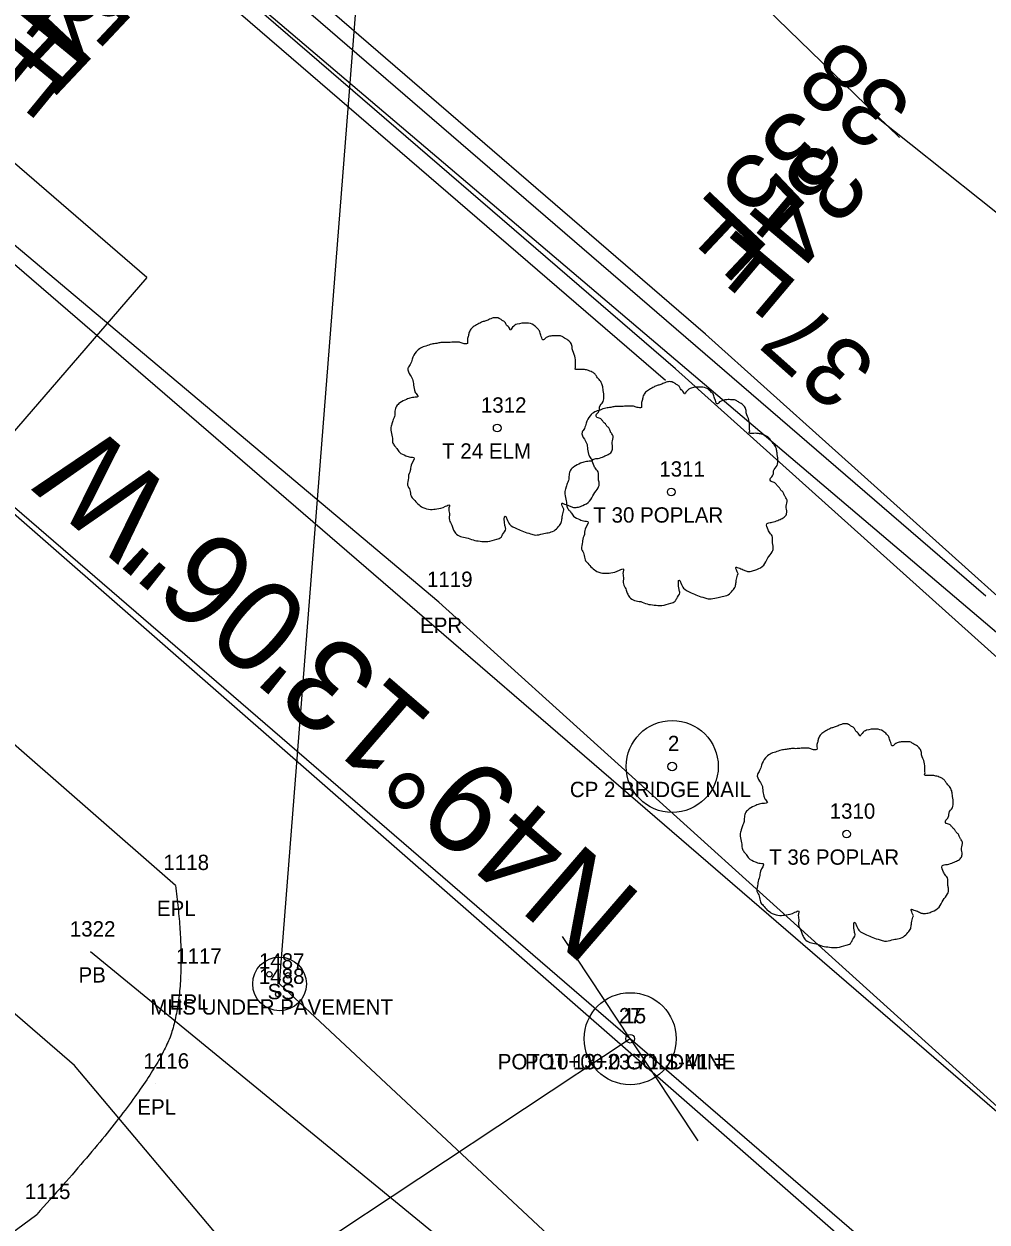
# Model space of a CAD drawing. Extents: x 1812113 to 1819860, y 1177395 to 1181185.
# Drawn here: x 1813790.4 to 1813853.2, y 1178629.6 to 1178707.7 of the extents above; entities that cross this region are included whole.
import ezdxf

# ---------------------------------------------------------------- set-up
doc = ezdxf.new("R2010")
doc.units = 0
for name, color, linetype in [('RD_EX_DR_Inlet', 7, 'Continuous'), ('RD_EX_DR_Pipe', 7, 'Continuous'), ('RD_EX_DR_Pipe_txCode', 7, 'Continuous'), ('RD_EX_DV_Prop', 7, 'Continuous'), ('RD_EX_Road', 7, 'Continuous'), ('RD_EX_Road_txCode', 7, 'Continuous'), ('RD_EX_UT', 7, 'Continuous'), ('RD_EX_UT_txCode', 7, 'Continuous'), ('RD_EX_VEG', 7, 'Continuous'), ('RD_EX_VEG_txCode', 7, 'Continuous'), ('RD_HC_CL', 7, 'Continuous'), ('RD_HC_Data', 7, 'Continuous'), ('RD_HC_Data_Tic', 7, 'Continuous'), ('RD_HC_txCode', 7, 'Continuous'), ('RD_PD_ALT1_TrvlWay', 7, 'Continuous'), ('RD_PD_ALT3_LnLine', 7, 'Continuous'), ('RD_PD_ALT4_LnLine', 7, 'Continuous'), ('RD_PD_BCA', 7, 'Continuous'), ('RD_PD_Bridge', 7, 'Continuous'), ('RD_PD_PatLn1', 7, 'Continuous'), ('RD_SMD_Locator', 7, 'Continuous')]:
    doc.layers.add(name, color=color, linetype=linetype)

msp = doc.modelspace()

# ---------------------------------------------------------------- linework, layer by layer
at = {"layer": 'RD_EX_DR_Inlet'}
for centre, radius in [((1813807.047, 1178645.143), 1.75), ((1813806.382, 1178645.773), 0.175), ((1813807.607, 1178645.703), 0.175), ((1813806.959, 1178644.478), 0.175)]:
    msp.add_circle(centre, radius, dxfattribs=at)
at = {"layer": 'RD_EX_DR_Pipe'}
msp.add_line((1813831.42, 1178617.18), (1813794.721, 1178647.236), dxfattribs=at)
at = {"layer": 'RD_EX_DV_Prop'}
msp.add_line((1813854.673, 1178667.319), (1813781.836, 1178729.192), dxfattribs=at)
at = {"layer": 'RD_EX_Road'}
for p, q in [((1813800.257, 1178651.571), (1813775.579, 1178673.127)), ((1813782.718, 1178623.8), (1813791.219, 1178630.116))]:
    msp.add_line(p, q, dxfattribs=at)
msp.add_lwpolyline([(1814076.449, 1178427.399), (1814038.861, 1178461.867), (1814001.829, 1178496.617), (1813965.148, 1178531.537), (1813928.085, 1178567.095), (1813892.01, 1178601.225), (1813854.538, 1178636.515), (1813817.438, 1178670.033), (1813779.867, 1178701.638)], dxfattribs=at)
msp.add_open_spline([(1813800.257, 1178651.571), (1813801.087, 1178645.461), (1813798.98, 1178638.625), (1813791.219, 1178630.116)], degree=2, dxfattribs=at)
at = {"layer": 'RD_EX_UT'}
msp.add_lwpolyline([(1814122.48, 1178351.311), (1814099.725, 1178371.678), (1813807.047, 1178645.143), (1813817.449, 1178777.901), (1813883.812, 1178790.874)], dxfattribs=at)
at = {"layer": 'RD_EX_VEG'}
for centre, radius in [((1813821.238, 1178681.396), 0.25), ((1813821.225, 1178681.377), 0.0001), ((1813832.586, 1178677.226), 0.25), ((1813832.574, 1178677.207), 0.0001), ((1813844.018, 1178654.917), 0.25), ((1813844.005, 1178654.898), 0.0001)]:
    msp.add_circle(centre, radius, dxfattribs=at)
for points in [[(1813821.37, 1178688.563), (1813821.07, 1178688.588), (1813820.745, 1178688.488), (1813820.495, 1178688.388), (1813820.27, 1178688.313), (1813820.045, 1178688.213), (1813819.745, 1178688.038), (1813819.52, 1178687.838), (1813819.395, 1178687.588), (1813819.345, 1178687.363), (1813819.295, 1178687.088), (1813819.295, 1178686.913), (1813819.171, 1178686.888), (1813819.021, 1178686.913), (1813818.771, 1178686.988), (1813818.521, 1178686.988), (1813818.271, 1178686.988), (1813817.921, 1178686.963), (1813817.571, 1178686.963), (1813817.296, 1178686.913), (1813816.971, 1178686.864), (1813816.597, 1178686.739), (1813816.247, 1178686.614), (1813815.947, 1178686.364), (1813815.697, 1178685.889), (1813815.572, 1178685.539), (1813815.422, 1178685.289), (1813815.572, 1178684.839), (1813815.747, 1178684.49), (1813815.772, 1178684.29), (1813815.847, 1178683.865), (1813815.947, 1178683.64), (1813816.072, 1178683.44), (1813815.997, 1178683.415), (1813815.622, 1178683.365), (1813815.322, 1178683.265), (1813814.897, 1178683.04), (1813814.672, 1178682.815), (1813814.572, 1178682.49), (1813814.548, 1178682.141), (1813814.448, 1178681.941), (1813814.373, 1178681.666), (1813814.348, 1178681.591), (1813814.298, 1178681.266), (1813814.398, 1178680.816), (1813814.423, 1178680.466), (1813814.548, 1178680.241), (1813814.697, 1178680.067), (1813814.872, 1178679.817), (1813815.272, 1178679.592), (1813815.597, 1178679.492), (1813815.797, 1178679.467), (1813815.622, 1178678.967), (1813815.572, 1178678.617), (1813815.447, 1178678.217), (1813815.447, 1178678.142), (1813815.397, 1178677.668), (1813815.547, 1178677.343), (1813815.622, 1178676.968), (1813815.797, 1178676.743), (1813816.072, 1178676.443), (1813816.397, 1178676.218), (1813816.897, 1178676.093), (1813817.296, 1178676.118), (1813817.871, 1178676.293), (1813818.121, 1178676.368), (1813818.096, 1178676.193), (1813818.121, 1178675.818), (1813818.121, 1178675.394), (1813818.271, 1178675.069), (1813818.371, 1178674.794), (1813818.521, 1178674.544), (1813818.846, 1178674.319), (1813819.245, 1178674.244), (1813819.67, 1178674.094), (1813820.12, 1178674.019), (1813820.62, 1178673.994), (1813821.22, 1178674.144), (1813821.494, 1178674.269), (1813821.594, 1178674.444), (1813821.794, 1178674.819), (1813821.744, 1178675.044), (1813821.769, 1178675.643), (1813821.869, 1178675.468), (1813822.044, 1178675.119), (1813822.544, 1178674.819), (1813822.944, 1178674.644), (1813823.419, 1178674.494), (1813823.719, 1178674.419), (1813824.193, 1178674.494), (1813824.568, 1178674.569), (1813824.943, 1178674.694), (1813825.243, 1178674.969), (1813825.418, 1178675.244), (1813825.468, 1178675.518), (1813825.543, 1178675.893), (1813825.593, 1178676.068)], [(1813825.593, 1178676.068), (1813825.518, 1178676.243), (1813825.468, 1178676.493), (1813825.543, 1178676.468), (1813825.718, 1178676.418), (1813825.993, 1178676.293), (1813826.217, 1178676.218), (1813826.542, 1178676.243), (1813826.817, 1178676.343), (1813827.267, 1178676.618), (1813827.542, 1178677.093), (1813827.817, 1178677.493), (1813827.892, 1178677.817), (1813827.842, 1178678.042), (1813827.817, 1178678.542), (1813827.617, 1178678.792), (1813827.567, 1178678.917), (1813827.467, 1178679.317), (1813827.542, 1178679.367), (1813827.817, 1178679.417), (1813828.192, 1178679.542), (1813828.466, 1178679.667), (1813828.691, 1178679.842), (1813828.766, 1178680.067), (1813828.741, 1178680.466), (1813828.791, 1178680.866), (1813828.716, 1178681.016), (1813828.616, 1178681.166), (1813828.541, 1178681.366), (1813828.391, 1178681.516), (1813828.292, 1178681.666), (1813828.192, 1178681.766), (1813828.067, 1178681.916), (1813827.892, 1178682.041), (1813827.742, 1178682.091), (1813827.692, 1178682.241), (1813827.842, 1178682.44), (1813827.892, 1178682.54), (1813827.917, 1178682.765), (1813828.142, 1178683.115), (1813828.192, 1178683.515), (1813828.142, 1178683.94), (1813828.092, 1178684.215), (1813827.942, 1178684.49), (1813827.742, 1178684.739), (1813827.617, 1178684.914), (1813827.442, 1178685.039), (1813827.117, 1178685.164), (1813826.867, 1178685.214), (1813826.517, 1178685.214), (1813826.317, 1178685.264), (1813826.342, 1178685.314), (1813826.342, 1178685.464), (1813826.342, 1178685.739), (1813826.267, 1178686.189), (1813826.117, 1178686.689), (1813826.117, 1178686.714), (1813826.017, 1178686.963), (1813825.793, 1178687.163), (1813825.618, 1178687.263), (1813825.418, 1178687.388), (1813825.168, 1178687.413), (1813824.868, 1178687.413), (1813824.593, 1178687.363), (1813824.393, 1178687.263), (1813824.218, 1178687.138), (1813824.143, 1178687.288), (1813824.043, 1178687.588), (1813823.993, 1178687.738), (1813823.843, 1178687.913), (1813823.619, 1178688.113), (1813823.169, 1178688.238), (1813822.544, 1178688.163), (1813822.244, 1178687.963), (1813822.094, 1178687.788), (1813822.044, 1178687.913), (1813821.844, 1178688.113), (1813821.744, 1178688.288), (1813821.569, 1178688.413), (1813821.42, 1178688.513), (1813821.32, 1178688.563)], [(1813832.718, 1178684.393), (1813832.418, 1178684.418), (1813832.094, 1178684.318), (1813831.844, 1178684.218), (1813831.619, 1178684.143), (1813831.394, 1178684.043), (1813831.094, 1178683.868), (1813830.869, 1178683.668), (1813830.744, 1178683.418), (1813830.694, 1178683.193), (1813830.644, 1178682.918), (1813830.644, 1178682.743), (1813830.519, 1178682.718), (1813830.369, 1178682.743), (1813830.119, 1178682.818), (1813829.869, 1178682.818), (1813829.62, 1178682.818), (1813829.27, 1178682.793), (1813828.92, 1178682.793), (1813828.645, 1178682.743), (1813828.32, 1178682.694), (1813827.945, 1178682.569), (1813827.595, 1178682.444), (1813827.296, 1178682.194), (1813827.046, 1178681.719), (1813826.921, 1178681.369), (1813826.771, 1178681.119), (1813826.921, 1178680.669), (1813827.096, 1178680.32), (1813827.121, 1178680.12), (1813827.196, 1178679.695), (1813827.296, 1178679.47), (1813827.421, 1178679.27), (1813827.346, 1178679.245), (1813826.971, 1178679.195), (1813826.671, 1178679.095), (1813826.246, 1178678.87), (1813826.021, 1178678.645), (1813825.921, 1178678.32), (1813825.896, 1178677.971), (1813825.796, 1178677.771), (1813825.721, 1178677.496), (1813825.696, 1178677.421), (1813825.646, 1178677.096), (1813825.746, 1178676.646), (1813825.771, 1178676.296), (1813825.896, 1178676.071), (1813826.046, 1178675.897), (1813826.221, 1178675.647), (1813826.621, 1178675.422), (1813826.946, 1178675.322), (1813827.146, 1178675.297), (1813826.971, 1178674.797), (1813826.921, 1178674.447), (1813826.796, 1178674.047), (1813826.796, 1178673.972), (1813826.746, 1178673.498), (1813826.896, 1178673.173), (1813826.971, 1178672.798), (1813827.146, 1178672.573), (1813827.421, 1178672.273), (1813827.745, 1178672.048), (1813828.245, 1178671.923), (1813828.645, 1178671.948), (1813829.22, 1178672.123), (1813829.47, 1178672.198), (1813829.445, 1178672.023), (1813829.47, 1178671.648), (1813829.47, 1178671.224), (1813829.62, 1178670.899), (1813829.72, 1178670.624), (1813829.869, 1178670.374), (1813830.194, 1178670.149), (1813830.594, 1178670.074), (1813831.019, 1178669.924), (1813831.469, 1178669.849), (1813831.969, 1178669.824), (1813832.568, 1178669.974), (1813832.843, 1178670.099), (1813832.943, 1178670.274), (1813833.143, 1178670.649), (1813833.093, 1178670.874), (1813833.118, 1178671.473), (1813833.218, 1178671.298), (1813833.393, 1178670.949), (1813833.893, 1178670.649), (1813834.293, 1178670.474), (1813834.767, 1178670.324), (1813835.067, 1178670.249), (1813835.542, 1178670.324), (1813835.917, 1178670.399), (1813836.292, 1178670.524), (1813836.592, 1178670.799), (1813836.766, 1178671.074), (1813836.816, 1178671.348), (1813836.891, 1178671.723), (1813836.941, 1178671.898)], [(1813836.941, 1178671.898), (1813836.866, 1178672.073), (1813836.816, 1178672.323), (1813836.891, 1178672.298), (1813837.066, 1178672.248), (1813837.341, 1178672.123), (1813837.566, 1178672.048), (1813837.891, 1178672.073), (1813838.166, 1178672.173), (1813838.616, 1178672.448), (1813838.891, 1178672.923), (1813839.165, 1178673.323), (1813839.24, 1178673.647), (1813839.19, 1178673.872), (1813839.165, 1178674.372), (1813838.965, 1178674.622), (1813838.915, 1178674.747), (1813838.816, 1178675.147), (1813838.891, 1178675.197), (1813839.165, 1178675.247), (1813839.54, 1178675.372), (1813839.815, 1178675.497), (1813840.04, 1178675.672), (1813840.115, 1178675.897), (1813840.09, 1178676.296), (1813840.14, 1178676.696), (1813840.065, 1178676.846), (1813839.965, 1178676.996), (1813839.89, 1178677.196), (1813839.74, 1178677.346), (1813839.64, 1178677.496), (1813839.54, 1178677.596), (1813839.415, 1178677.746), (1813839.24, 1178677.871), (1813839.09, 1178677.921), (1813839.04, 1178678.071), (1813839.19, 1178678.27), (1813839.24, 1178678.37), (1813839.265, 1178678.595), (1813839.49, 1178678.945), (1813839.54, 1178679.345), (1813839.49, 1178679.77), (1813839.44, 1178680.045), (1813839.29, 1178680.32), (1813839.09, 1178680.569), (1813838.965, 1178680.744), (1813838.791, 1178680.869), (1813838.466, 1178680.994), (1813838.216, 1178681.044), (1813837.866, 1178681.044), (1813837.666, 1178681.094), (1813837.691, 1178681.144), (1813837.691, 1178681.294), (1813837.691, 1178681.569), (1813837.616, 1178682.019), (1813837.466, 1178682.519), (1813837.466, 1178682.544), (1813837.366, 1178682.793), (1813837.141, 1178682.993), (1813836.966, 1178683.093), (1813836.766, 1178683.218), (1813836.517, 1178683.243), (1813836.217, 1178683.243), (1813835.942, 1178683.193), (1813835.742, 1178683.093), (1813835.567, 1178682.968), (1813835.492, 1178683.118), (1813835.392, 1178683.418), (1813835.342, 1178683.568), (1813835.192, 1178683.743), (1813834.967, 1178683.943), (1813834.517, 1178684.068), (1813833.893, 1178683.993), (1813833.593, 1178683.793), (1813833.443, 1178683.618), (1813833.393, 1178683.743), (1813833.193, 1178683.943), (1813833.093, 1178684.118), (1813832.918, 1178684.243), (1813832.768, 1178684.343), (1813832.668, 1178684.393)], [(1813844.15, 1178662.084), (1813843.85, 1178662.109), (1813843.525, 1178662.009), (1813843.275, 1178661.909), (1813843.05, 1178661.834), (1813842.826, 1178661.734), (1813842.526, 1178661.559), (1813842.301, 1178661.359), (1813842.176, 1178661.11), (1813842.126, 1178660.885), (1813842.076, 1178660.61), (1813842.076, 1178660.435), (1813841.951, 1178660.41), (1813841.801, 1178660.435), (1813841.551, 1178660.51), (1813841.301, 1178660.51), (1813841.051, 1178660.51), (1813840.701, 1178660.485), (1813840.352, 1178660.485), (1813840.077, 1178660.435), (1813839.752, 1178660.385), (1813839.377, 1178660.26), (1813839.027, 1178660.135), (1813838.727, 1178659.885), (1813838.477, 1178659.41), (1813838.352, 1178659.06), (1813838.203, 1178658.811), (1813838.352, 1178658.361), (1813838.527, 1178658.011), (1813838.552, 1178657.811), (1813838.627, 1178657.386), (1813838.727, 1178657.161), (1813838.852, 1178656.961), (1813838.777, 1178656.936), (1813838.402, 1178656.886), (1813838.103, 1178656.786), (1813837.678, 1178656.562), (1813837.453, 1178656.337), (1813837.353, 1178656.012), (1813837.328, 1178655.662), (1813837.228, 1178655.462), (1813837.153, 1178655.187), (1813837.128, 1178655.112), (1813837.078, 1178654.787), (1813837.178, 1178654.337), (1813837.203, 1178653.988), (1813837.328, 1178653.763), (1813837.478, 1178653.588), (1813837.653, 1178653.338), (1813838.053, 1178653.113), (1813838.377, 1178653.013), (1813838.577, 1178652.988), (1813838.402, 1178652.488), (1813838.352, 1178652.138), (1813838.228, 1178651.739), (1813838.228, 1178651.664), (1813838.178, 1178651.189), (1813838.327, 1178650.864), (1813838.402, 1178650.489), (1813838.577, 1178650.264), (1813838.852, 1178649.964), (1813839.177, 1178649.74), (1813839.677, 1178649.615), (1813840.077, 1178649.64), (1813840.652, 1178649.814), (1813840.901, 1178649.889), (1813840.876, 1178649.715), (1813840.901, 1178649.34), (1813840.901, 1178648.915), (1813841.051, 1178648.59), (1813841.151, 1178648.315), (1813841.301, 1178648.065), (1813841.626, 1178647.84), (1813842.026, 1178647.765), (1813842.451, 1178647.615), (1813842.901, 1178647.54), (1813843.4, 1178647.515), (1813844, 1178647.665), (1813844.275, 1178647.79), (1813844.375, 1178647.965), (1813844.575, 1178648.34), (1813844.525, 1178648.565), (1813844.55, 1178649.165), (1813844.65, 1178648.99), (1813844.825, 1178648.64), (1813845.324, 1178648.34), (1813845.724, 1178648.165), (1813846.199, 1178648.015), (1813846.499, 1178647.94), (1813846.974, 1178648.015), (1813847.349, 1178648.09), (1813847.723, 1178648.215), (1813848.023, 1178648.49), (1813848.198, 1178648.765), (1813848.248, 1178649.04), (1813848.323, 1178649.415), (1813848.373, 1178649.59)], [(1813848.373, 1178649.59), (1813848.298, 1178649.765), (1813848.248, 1178650.014), (1813848.323, 1178649.989), (1813848.498, 1178649.939), (1813848.773, 1178649.814), (1813848.998, 1178649.74), (1813849.323, 1178649.765), (1813849.598, 1178649.864), (1813850.047, 1178650.139), (1813850.322, 1178650.614), (1813850.597, 1178651.014), (1813850.672, 1178651.339), (1813850.622, 1178651.564), (1813850.597, 1178652.063), (1813850.397, 1178652.313), (1813850.347, 1178652.438), (1813850.247, 1178652.838), (1813850.322, 1178652.888), (1813850.597, 1178652.938), (1813850.972, 1178653.063), (1813851.247, 1178653.188), (1813851.472, 1178653.363), (1813851.547, 1178653.588), (1813851.522, 1178653.988), (1813851.572, 1178654.387), (1813851.497, 1178654.537), (1813851.397, 1178654.687), (1813851.322, 1178654.887), (1813851.172, 1178655.037), (1813851.072, 1178655.187), (1813850.972, 1178655.287), (1813850.847, 1178655.437), (1813850.672, 1178655.562), (1813850.522, 1178655.612), (1813850.472, 1178655.762), (1813850.622, 1178655.962), (1813850.672, 1178656.062), (1813850.697, 1178656.287), (1813850.922, 1178656.636), (1813850.972, 1178657.036), (1813850.922, 1178657.461), (1813850.872, 1178657.736), (1813850.722, 1178658.011), (1813850.522, 1178658.261), (1813850.397, 1178658.436), (1813850.222, 1178658.561), (1813849.897, 1178658.686), (1813849.648, 1178658.736), (1813849.298, 1178658.736), (1813849.098, 1178658.786), (1813849.123, 1178658.836), (1813849.123, 1178658.985), (1813849.123, 1178659.26), (1813849.048, 1178659.71), (1813848.898, 1178660.21), (1813848.898, 1178660.235), (1813848.798, 1178660.485), (1813848.573, 1178660.685), (1813848.398, 1178660.785), (1813848.198, 1178660.91), (1813847.948, 1178660.935), (1813847.648, 1178660.935), (1813847.374, 1178660.885), (1813847.174, 1178660.785), (1813846.999, 1178660.66), (1813846.924, 1178660.81), (1813846.824, 1178661.11), (1813846.774, 1178661.259), (1813846.624, 1178661.434), (1813846.399, 1178661.634), (1813845.949, 1178661.759), (1813845.324, 1178661.684), (1813845.025, 1178661.484), (1813844.875, 1178661.309), (1813844.825, 1178661.434), (1813844.625, 1178661.634), (1813844.525, 1178661.809), (1813844.35, 1178661.934), (1813844.2, 1178662.034), (1813844.1, 1178662.084)]]:
    msp.add_spline(points, degree=3, dxfattribs=at)
at = {"layer": 'RD_HC_CL'}
for p, q in [((1813850.516, 1178623.797), (1813755.38, 1178705.862)), ((1813829.909, 1178641.573), (1813743.828, 1178584.56))]:
    msp.add_line(p, q, dxfattribs=at)
at = {"layer": 'RD_HC_Data'}
for centre, radius in [((1813832.652, 1178659.325), 3), ((1813832.652, 1178659.325), 0.282), ((1813829.909, 1178641.573), 3), ((1813829.909, 1178641.573), 3), ((1813829.909, 1178641.573), 0.282), ((1813829.909, 1178641.573), 0.282)]:
    msp.add_circle(centre, radius, dxfattribs=at)
at = {"layer": 'RD_HC_Data_Tic'}
for q in [(1813825.492, 1178648.242), (1813834.327, 1178634.903)]:
    msp.add_line((1813829.909, 1178641.573), q, dxfattribs=at)
at = {"layer": 'RD_PD_ALT1_TrvlWay'}
msp.add_line((1813858.354, 1178632.883), (1813779.98, 1178700.49), dxfattribs=at)
at = {"layer": 'RD_PD_ALT3_LnLine'}
for p, q in [((1813834.823, 1178687.519), (1813796.963, 1178720.177)), ((1813832.863, 1178685.247), (1813795.003, 1178717.906)), ((1813872.03, 1178654.102), (1813834.823, 1178687.519)), ((1813870.07, 1178651.831), (1813832.863, 1178685.247)), ((1813793.673, 1178639.815), (1813755.812, 1178672.473)), ((1813826.308, 1178601.098), (1813793.673, 1178639.815))]:
    msp.add_line(p, q, dxfattribs=at)
at = {"layer": 'RD_PD_ALT4_LnLine'}
for p, q in [((1813834.17, 1178686.761), (1813796.309, 1178719.42)), ((1813832.21, 1178684.49), (1813794.35, 1178717.149)), ((1813853.1, 1178670.432), (1813834.17, 1178686.761))]:
    msp.add_line(p, q, dxfattribs=at)
at = {"layer": 'RD_PD_BCA'}
for p, q in [((1813847.464, 1178700.339), (1813817.015, 1178729.964)), ((1813885.131, 1178670.514), (1813845.964, 1178701.658))]:
    msp.add_line(p, q, dxfattribs=at)
at = {"layer": 'RD_PD_Bridge'}
for q in [(1813783.246, 1178704.276), (1813774.756, 1178663.814)]:
    msp.add_line((1813798.39, 1178691.213), q, dxfattribs=at)
at = {"layer": 'RD_PD_PatLn1'}
msp.add_line((1813775.635, 1178688.143), (1813886.049, 1178591.554), dxfattribs=at)
at = {"layer": 'RD_SMD_Locator'}
for centre in [(1813817.438, 1178670.033), (1813832.652, 1178659.325), (1813800.257, 1178651.571), (1813794.721, 1178647.236), (1813801.087, 1178645.461), (1813807.047, 1178645.143), (1813829.909, 1178641.573), (1813829.909, 1178641.573), (1813798.98, 1178638.625), (1813791.219, 1178630.116)]:
    msp.add_circle(centre, 0.001, dxfattribs=at)

# ---------------------------------------------------------------- texts
at = {"layer": 'RD_EX_DR_Pipe_txCode'}
for s, p in [('1322', (1813793.375, 1178648.236)), ('PB', (1813793.941, 1178645.236))]:
    msp.add_text(s, height=1, dxfattribs=at).set_placement(p)
at = {"layer": 'RD_EX_Road_txCode'}
for s, p in [('1119', (1813816.659, 1178671.033)), ('EPR', (1813816.21, 1178668.033)), ('1118', (1813799.477, 1178652.571)), ('EPL', (1813799.052, 1178649.571)), ('1117', (1813800.307, 1178646.461)), ('EPL', (1813799.882, 1178643.461)), ('1116', (1813798.176, 1178639.625)), ('EPL', (1813797.775, 1178636.625)), ('1115', (1813790.439, 1178631.116))]:
    msp.add_text(s, height=1, dxfattribs=at).set_placement(p)
at = {"layer": 'RD_EX_UT_txCode'}
for s, p in [('1487', (1813805.7, 1178646.143)), ('1488', (1813805.7, 1178645.143)), ('SS', (1813806.267, 1178644.143)), ('MHS UNDER PAVEMENT', (1813798.622, 1178643.143))]:
    msp.add_text(s, height=1, dxfattribs=at).set_placement(p)
at = {"layer": 'RD_EX_VEG_txCode'}
for s, p in [('1312', (1813820.175, 1178682.396)), ('T 24 ELM', (1813817.647, 1178679.396)), ('1311', (1813831.807, 1178678.226)), ('T 30 POPLAR', (1813827.508, 1178675.226)), ('1310', (1813842.916, 1178655.917)), ('T 36 POPLAR', (1813838.971, 1178652.917))]:
    msp.add_text(s, height=1, dxfattribs=at).set_placement(p)
at = {"layer": 'RD_HC_Data'}
msp.add_text('N49%%d13\'06"W', height=6, rotation=139.21843, dxfattribs=at).set_placement((1813830.878, 1178650.758))
at = {"layer": 'RD_HC_txCode'}
for s, p in [('2', (1813832.369, 1178660.325)), ('CP 2 BRIDGE NAIL', (1813825.975, 1178657.325)), ('27', (1813829.177, 1178642.573)), ('15', (1813829.46, 1178642.573)), ('POT 10+00.0 GOLDMINE', (1813821.275, 1178639.573)), ('POT 13+23.71 S-41 =', (1813823.043, 1178639.573))]:
    msp.add_text(s, height=1, dxfattribs=at).set_placement(p)
at = {"layer": 'RD_PD_ALT3_LnLine'}
for s, height, rotation, p in [('35F', 5, 226.72337, (1813796.593, 1178714.722)), ('38', 4.5, 138.8497, (1813848.52, 1178702.587)), ('35F', 5, 226.72337, (1813840.565, 1178702.623))]:
    msp.add_text(s, height=height, rotation=rotation, dxfattribs=at).set_placement(p)
at = {"layer": 'RD_PD_ALT4_LnLine'}
for s, height, rotation, p in [('34F', 5, 230.65202, (1813794.271, 1178713.486)), ('34F', 5, 229.89092, (1813841.947, 1178700.39)), ('37', 4.5, 138.34632, (1813846.175, 1178685.616))]:
    msp.add_text(s, height=height, rotation=rotation, dxfattribs=at).set_placement(p)

doc.saveas('drawing.dxf')
